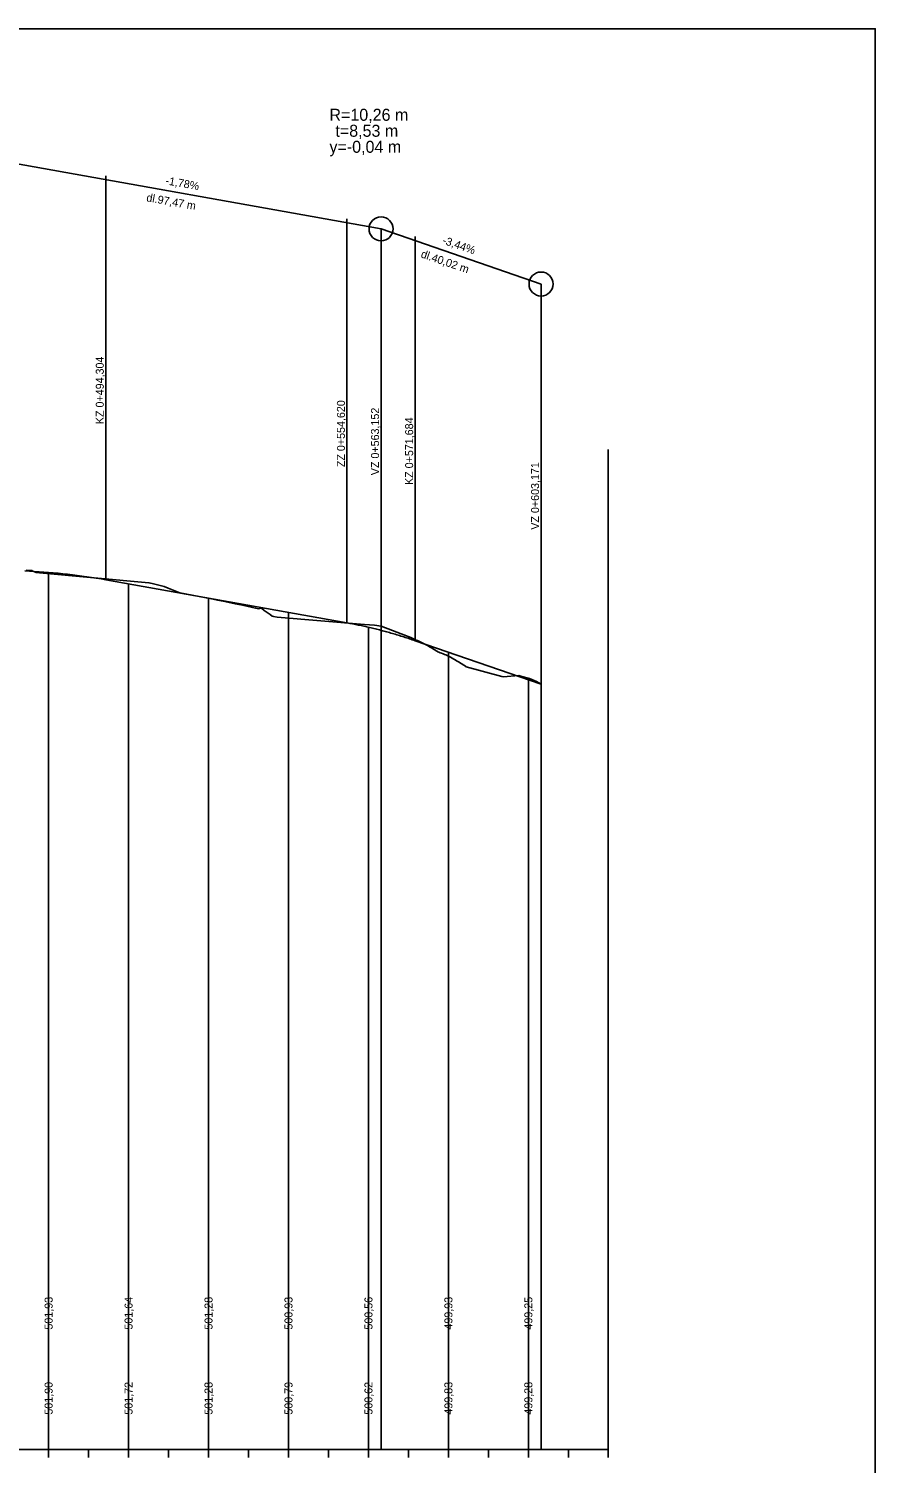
# Model space of a CAD drawing. Extents: x -632716 to -629545, y -1094726 to -1088285.
# Drawn here: x -631942.9 to -631731.1, y -1088643.3 to -1088284.6 of the extents above; entities that cross this region are included whole.
import ezdxf

# ---------------------------------------------------------------- set-up
doc = ezdxf.new("R2010")
doc.units = 0
for name, color, linetype in [('20', 7, 'Continuous'), ('Default', 7, 'Continuous'), ('formát', 7, 'Continuous'), ('NIVELETA_VYSKY', 7, 'Continuous'), ('REZ_TENKA', 7, 'Continuous'), ('REZ_TLUSTA', 7, 'Continuous'), ('SKLONY_NIVELETA', 7, 'Continuous'), ('SKLONY_POPIS', 7, 'Continuous'), ('TECNY_NIVELETA', 7, 'Continuous'), ('TEREN_VYSKY', 7, 'Continuous'), ('VOZOVKA', 7, 'Continuous')]:
    doc.layers.add(name, color=color, linetype=linetype)

msp = doc.modelspace()

# ---------------------------------------------------------------- linework, layer by layer
at = {"layer": '20'}
for points in [[(-631797.9, -1088389.83), (-631797.9, -1088589.83), (-631797.9, -1088639.83), (-631797.9, -1088579.83)], [(-631937.9, -1088420.56), (-631937.9, -1088589.83), (-631937.9, -1088639.83), (-631937.9, -1088579.83)], [(-631917.9, -1088423.42), (-631917.9, -1088589.83), (-631917.9, -1088639.83), (-631917.9, -1088579.83)], [(-631897.9, -1088426.99), (-631897.9, -1088589.83), (-631897.9, -1088639.83), (-631897.9, -1088579.83)], [(-631877.9, -1088430.55), (-631877.9, -1088589.83), (-631877.9, -1088639.83), (-631877.9, -1088579.83)], [(-631857.9, -1088434.26), (-631857.9, -1088589.83), (-631857.9, -1088639.83), (-631857.9, -1088579.83)], [(-631837.9, -1088440.48), (-631837.9, -1088589.83), (-631837.9, -1088639.83), (-631837.9, -1088579.83)], [(-631817.9, -1088447.37), (-631817.9, -1088589.83), (-631817.9, -1088639.83), (-631817.9, -1088579.83)]]:
    msp.add_lwpolyline(points, dxfattribs=at)
at = {"layer": 'Default'}
for p, q in [((-631923.6, -1088422.41), (-631863.28, -1088433.16)), ((-631923.6, -1088422.41), (-631863.28, -1088433.16)), ((-631846.22, -1088437.62), (-631814.73, -1088448.47)), ((-631846.22, -1088437.62), (-631814.73, -1088448.47))]:
    msp.add_line(p, q, dxfattribs=at)
for points in [[(-631943.88, -1088420.2), (-631942.68, -1088420.25), (-631941.49, -1088420.31), (-631940.3, -1088420.38), (-631939.1, -1088420.47), (-631937.91, -1088420.56), (-631936.72, -1088420.66), (-631935.53, -1088420.77), (-631934.33, -1088420.89), (-631933.14, -1088421.02), (-631931.95, -1088421.16), (-631930.76, -1088421.31), (-631929.56, -1088421.47), (-631928.37, -1088421.64), (-631927.18, -1088421.81), (-631925.98, -1088422), (-631924.79, -1088422.2), (-631923.6, -1088422.41)], [(-631943.88, -1088420.2), (-631942.68, -1088420.25), (-631941.49, -1088420.31), (-631940.3, -1088420.38), (-631939.1, -1088420.47), (-631937.91, -1088420.56), (-631936.72, -1088420.66), (-631935.53, -1088420.77), (-631934.33, -1088420.89), (-631933.14, -1088421.02), (-631931.95, -1088421.16), (-631930.76, -1088421.31), (-631929.56, -1088421.47), (-631928.37, -1088421.64), (-631927.18, -1088421.81), (-631925.98, -1088422), (-631924.79, -1088422.2), (-631923.6, -1088422.41)], [(-631863.28, -1088433.16), (-631862.93, -1088433.22), (-631862.57, -1088433.29), (-631862.22, -1088433.36), (-631861.86, -1088433.42), (-631861.51, -1088433.49), (-631861.15, -1088433.56), (-631860.79, -1088433.63), (-631860.44, -1088433.71), (-631860.08, -1088433.78), (-631859.73, -1088433.85), (-631859.37, -1088433.93), (-631859.02, -1088434.01), (-631858.66, -1088434.09), (-631858.31, -1088434.17), (-631857.95, -1088434.25), (-631857.6, -1088434.33), (-631857.24, -1088434.41), (-631856.88, -1088434.5), (-631856.53, -1088434.59), (-631856.17, -1088434.67), (-631855.82, -1088434.76), (-631855.46, -1088434.85), (-631855.11, -1088434.94), (-631854.4, -1088435.13), (-631854.04, -1088435.22), (-631853.68, -1088435.32), (-631853.33, -1088435.42), (-631852.97, -1088435.51), (-631852.62, -1088435.61), (-631852.26, -1088435.72), (-631851.91, -1088435.82), (-631851.55, -1088435.92), (-631851.2, -1088436.03), (-631850.84, -1088436.13), (-631850.49, -1088436.24), (-631850.13, -1088436.35), (-631849.77, -1088436.46), (-631849.42, -1088436.57), (-631849.06, -1088436.68), (-631848.71, -1088436.79), (-631848.35, -1088436.91), (-631848, -1088437.02), (-631847.64, -1088437.14), (-631847.29, -1088437.26), (-631846.93, -1088437.38), (-631846.57, -1088437.5), (-631846.22, -1088437.62)], [(-631863.28, -1088433.16), (-631862.93, -1088433.22), (-631862.57, -1088433.29), (-631862.22, -1088433.36), (-631861.86, -1088433.42), (-631861.51, -1088433.49), (-631861.15, -1088433.56), (-631860.79, -1088433.63), (-631860.44, -1088433.71), (-631860.08, -1088433.78), (-631859.73, -1088433.85), (-631859.37, -1088433.93), (-631859.02, -1088434.01), (-631858.66, -1088434.09), (-631858.31, -1088434.17), (-631857.95, -1088434.25), (-631857.6, -1088434.33), (-631857.24, -1088434.41), (-631856.88, -1088434.5), (-631856.53, -1088434.59), (-631856.17, -1088434.67), (-631855.82, -1088434.76), (-631855.46, -1088434.85), (-631855.11, -1088434.94), (-631854.4, -1088435.13), (-631854.04, -1088435.22), (-631853.68, -1088435.32), (-631853.33, -1088435.42), (-631852.97, -1088435.51), (-631852.62, -1088435.61), (-631852.26, -1088435.72), (-631851.91, -1088435.82), (-631851.55, -1088435.92), (-631851.2, -1088436.03), (-631850.84, -1088436.13), (-631850.49, -1088436.24), (-631850.13, -1088436.35), (-631849.77, -1088436.46), (-631849.42, -1088436.57), (-631849.06, -1088436.68), (-631848.71, -1088436.79), (-631848.35, -1088436.91), (-631848, -1088437.02), (-631847.64, -1088437.14), (-631847.29, -1088437.26), (-631846.93, -1088437.38), (-631846.57, -1088437.5), (-631846.22, -1088437.62)]]:
    msp.add_lwpolyline(points, dxfattribs=at)
at = {"layer": 'formát'}
msp.add_lwpolyline([(-632571.12, -1088878.64), (-631731.12, -1088878.64), (-631731.12, -1088284.64), (-632571.12, -1088284.64)], close=True, dxfattribs=at)
at = {"layer": 'REZ_TENKA'}
for p, q in [((-631937.9, -1088641.83), (-631937.9, -1088639.83)), ((-631927.9, -1088641.83), (-631927.9, -1088639.83)), ((-631907.9, -1088641.83), (-631907.9, -1088639.83)), ((-631897.9, -1088641.83), (-631897.9, -1088639.83)), ((-631887.9, -1088641.83), (-631887.9, -1088639.83)), ((-631877.9, -1088641.83), (-631877.9, -1088639.83)), ((-631867.9, -1088641.83), (-631867.9, -1088639.83)), ((-631857.9, -1088641.83), (-631857.9, -1088639.83)), ((-631847.9, -1088641.83), (-631847.9, -1088639.83)), ((-631837.9, -1088641.83), (-631837.9, -1088639.83)), ((-631827.9, -1088641.83), (-631827.9, -1088639.83)), ((-631807.9, -1088641.83), (-631807.9, -1088639.83)), ((-631797.9, -1088641.83), (-631797.9, -1088639.83))]:
    msp.add_line(p, q, dxfattribs=at)
at = {"layer": 'REZ_TLUSTA'}
for p, q in [((-631917.9, -1088641.83), (-631917.9, -1088637.83)), ((-631817.9, -1088641.83), (-631817.9, -1088637.83)), ((-632417.9, -1088639.83), (-631797.9, -1088639.83))]:
    msp.add_line(p, q, dxfattribs=at)
at = {"layer": 'SKLONY_NIVELETA'}
for p, q in [((-631952.22, -1088317.31), (-631854.75, -1088334.68)), ((-631854.75, -1088334.68), (-631854.75, -1088639.83)), ((-631854.75, -1088334.68), (-631814.73, -1088348.47)), ((-631814.73, -1088348.47), (-631814.73, -1088639.83)), ((-631923.6, -1088422.41), (-631863.28, -1088433.16)), ((-631846.22, -1088437.62), (-631814.73, -1088448.47))]:
    msp.add_line(p, q, dxfattribs=at)
for points in [[(-631943.88, -1088420.2), (-631942.68, -1088420.25), (-631941.49, -1088420.31), (-631940.3, -1088420.38), (-631939.1, -1088420.47), (-631937.91, -1088420.56), (-631936.72, -1088420.66), (-631935.53, -1088420.77), (-631934.33, -1088420.89), (-631933.14, -1088421.02), (-631931.95, -1088421.16), (-631930.76, -1088421.31), (-631929.56, -1088421.47), (-631928.37, -1088421.64), (-631927.18, -1088421.81), (-631925.98, -1088422), (-631924.79, -1088422.2), (-631923.6, -1088422.41)], [(-631863.28, -1088433.16), (-631862.93, -1088433.22), (-631862.57, -1088433.29), (-631862.22, -1088433.36), (-631861.86, -1088433.42), (-631861.51, -1088433.49), (-631861.15, -1088433.56), (-631860.79, -1088433.63), (-631860.44, -1088433.71), (-631860.08, -1088433.78), (-631859.73, -1088433.85), (-631859.37, -1088433.93), (-631859.02, -1088434.01), (-631858.66, -1088434.09), (-631858.31, -1088434.17), (-631857.95, -1088434.25), (-631857.6, -1088434.33), (-631857.24, -1088434.41), (-631856.88, -1088434.5), (-631856.53, -1088434.59), (-631856.17, -1088434.67), (-631855.82, -1088434.76), (-631855.46, -1088434.85), (-631855.11, -1088434.94), (-631854.4, -1088435.13), (-631854.04, -1088435.22), (-631853.68, -1088435.32), (-631853.33, -1088435.42), (-631852.97, -1088435.51), (-631852.62, -1088435.61), (-631852.26, -1088435.72), (-631851.91, -1088435.82), (-631851.55, -1088435.92), (-631851.2, -1088436.03), (-631850.84, -1088436.13), (-631850.49, -1088436.24), (-631850.13, -1088436.35), (-631849.77, -1088436.46), (-631849.42, -1088436.57), (-631849.06, -1088436.68), (-631848.71, -1088436.79), (-631848.35, -1088436.91), (-631848, -1088437.02), (-631847.64, -1088437.14), (-631847.29, -1088437.26), (-631846.93, -1088437.38), (-631846.57, -1088437.5), (-631846.22, -1088437.62)]]:
    msp.add_lwpolyline(points, dxfattribs=at)
for centre in [(-631854.75, -1088334.68), (-631814.73, -1088348.47)]:
    msp.add_circle(centre, 3, dxfattribs=at)
at = {"layer": 'TECNY_NIVELETA'}
for p, q in [((-631923.6, -1088422.41), (-631923.6, -1088321.41)), ((-631863.28, -1088433.16), (-631863.28, -1088332.16)), ((-631854.75, -1088334.68), (-631854.75, -1088334.68)), ((-631846.22, -1088437.62), (-631846.22, -1088336.62)), ((-631814.73, -1088348.47), (-631814.73, -1088348.47))]:
    msp.add_line(p, q, dxfattribs=at)
at = {"layer": 'VOZOVKA'}
msp.add_lwpolyline([(-631943.5, -1088420), (-631942.66, -1088420.05), (-631942.11, -1088420.08), (-631941.83, -1088420.21), (-631941.05, -1088420.6), (-631941, -1088420.6), (-631940.16, -1088420.68), (-631912.8, -1088423.12), (-631911.97, -1088423.33), (-631909.97, -1088423.82), (-631909, -1088424.05), (-631907.97, -1088424.46), (-631905.05, -1088425.62), (-631897.12, -1088427.19), (-631895.66, -1088427.48), (-631894.2, -1088427.78), (-631892.74, -1088428.08), (-631891.93, -1088428.25), (-631891.27, -1088428.38), (-631889.81, -1088428.69), (-631888.35, -1088429), (-631886.89, -1088429.32), (-631885.43, -1088429.64), (-631885.36, -1088429.65), (-631884.67, -1088429.53), (-631883.96, -1088430.04), (-631882.5, -1088431.11), (-631881.98, -1088431.49), (-631881.64, -1088431.55), (-631880.77, -1088431.72), (-631858.88, -1088433.6), (-631856.39, -1088433.75), (-631854.7, -1088433.98), (-631847.99, -1088436.55), (-631847.33, -1088436.84), (-631847, -1088436.99), (-631846.66, -1088437.14), (-631846.33, -1088437.3), (-631846, -1088437.45), (-631845.66, -1088437.6), (-631845.33, -1088437.76), (-631845, -1088437.92), (-631844.66, -1088438.08), (-631844.33, -1088438.24), (-631844, -1088438.41), (-631843.66, -1088438.58), (-631843.62, -1088438.6), (-631843.33, -1088438.75), (-631843, -1088438.94), (-631842.66, -1088439.12), (-631842.33, -1088439.31), (-631841.99, -1088439.51), (-631841.65, -1088439.72), (-631841.3, -1088439.93), (-631840.96, -1088440.14), (-631840.62, -1088440.36), (-631840.52, -1088440.42), (-631840.28, -1088440.5), (-631839.94, -1088440.63), (-631839.59, -1088440.76), (-631839.25, -1088440.89), (-631838.91, -1088441.04), (-631838.57, -1088441.19), (-631838.23, -1088441.35), (-631837.9, -1088441.51), (-631837.57, -1088441.68), (-631837.23, -1088441.86), (-631836.9, -1088442.04), (-631836.79, -1088442.1), (-631836.57, -1088442.23), (-631836.23, -1088442.42), (-631835.9, -1088442.62), (-631835.57, -1088442.82), (-631835.23, -1088443.02), (-631834.9, -1088443.22), (-631834.57, -1088443.43), (-631834.23, -1088443.63), (-631833.9, -1088443.84), (-631833.57, -1088444.05), (-631833.44, -1088444.13), (-631824.52, -1088446.55), (-631824.18, -1088446.63), (-631820.25, -1088446.35), (-631819.52, -1088446.61), (-631817.6, -1088447.11), (-631815.88, -1088447.79), (-631814.74, -1088448.47), (-631814.73, -1088448.47)], dxfattribs=at)

# ---------------------------------------------------------------- texts
at = {"layer": 'NIVELETA_VYSKY'}
for s, p in [('501,93', (-631936.9, -1088609.83)), ('501,64', (-631916.9, -1088609.83)), ('501,28', (-631896.9, -1088609.83)), ('500,93', (-631876.9, -1088609.83)), ('500,56', (-631856.9, -1088609.83)), ('499,93', (-631836.9, -1088609.83)), ('499,25', (-631816.9, -1088609.83))]:
    msp.add_text(s, height=2, rotation=90, dxfattribs=at).set_placement(p)
at = {"layer": 'SKLONY_POPIS'}
for s, p in [('R=10,26 m', (-631867.66, -1088307.66)), ('t=8,53 m', (-631866.17, -1088311.66)), ('y=-0,04 m', (-631867.66, -1088315.66))]:
    msp.add_text(s, height=3, dxfattribs=at).set_placement(p)
for s, rotation, p in [('-1,78%', 349.8938, (-631908.77, -1088323.53)), ('dl.97,47 m', 349.8938, (-631913.55, -1088327.76)), ('dl.40,02 m', 340.9922, (-631844.96, -1088341.76)), ('-3,44%', 340.9922, (-631839.58, -1088338.32)), ('KZ 0+494,304', 90, (-631924.1, -1088383.49)), ('ZZ 0+554,620', 90, (-631863.78, -1088394.24)), ('VZ 0+563,152', 90, (-631855.25, -1088396.26)), ('KZ 0+571,684', 90, (-631846.72, -1088398.7)), ('VZ 0+603,171', 90, (-631815.23, -1088409.88))]:
    msp.add_text(s, height=2, rotation=rotation, dxfattribs=at).set_placement(p)
at = {"layer": 'TEREN_VYSKY'}
for s, p in [('501,90', (-631936.9, -1088631.09)), ('501,72', (-631916.9, -1088631.09)), ('501,28', (-631896.9, -1088631.09)), ('500,79', (-631876.9, -1088631.09)), ('500,62', (-631856.9, -1088631.09)), ('499,83', (-631836.9, -1088631.09)), ('499,28', (-631816.9, -1088631.09))]:
    msp.add_text(s, height=2, rotation=90, dxfattribs=at).set_placement(p)

doc.saveas('drawing.dxf')
